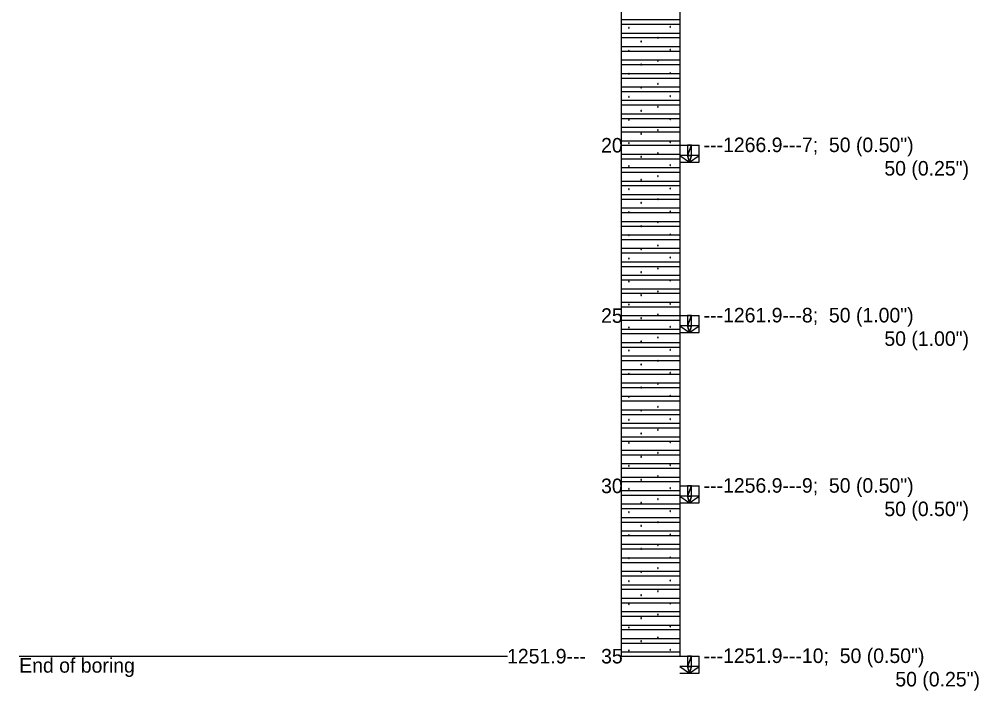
# Model space of a CAD drawing. Extents: x -6 to 173, y 24 to 64.
# Drawn here: x 138.22 to 146.4, y 39.13 to 44.86 of the extents above; entities that cross this region are included whole.
import ezdxf

# ---------------------------------------------------------------- set-up
doc = ezdxf.new("R2010")
doc.units = 0

msp = doc.modelspace()

# ---------------------------------------------------------------- linework, layer by layer
for points in [[(143.3519, 49.5977), (143.3519, 39.4233)], [(143.8519, 49.5977), (143.8519, 39.4233)], [(143.3519, 44.8563), (143.8519, 44.8563)], [(143.3519, 44.817), (143.8519, 44.817)], [(143.4223, 44.7872), (143.4206, 44.79), (143.4174, 44.79), (143.4157, 44.7872), (143.4174, 44.7843), (143.4206, 44.7843), (143.4223, 44.7872)], [(143.775, 44.7937), (143.7734, 44.7966), (143.7701, 44.7966), (143.7685, 44.7937), (143.7701, 44.7908), (143.7734, 44.7908), (143.775, 44.7937)], [(143.3519, 44.7415), (143.8519, 44.7415)], [(143.3519, 44.7021), (143.8519, 44.7021)], [(143.6695, 44.7012), (143.6679, 44.704), (143.6646, 44.704), (143.663, 44.7012), (143.6646, 44.6983), (143.6679, 44.6983), (143.6695, 44.7012)], [(143.3519, 44.6267), (143.8519, 44.6267)], [(143.5269, 44.6693), (143.5253, 44.6721), (143.522, 44.6721), (143.5204, 44.6693), (143.522, 44.6664), (143.5253, 44.6664), (143.5269, 44.6693)], [(143.3519, 44.5873), (143.8519, 44.5873)], [(143.4223, 44.5903), (143.4206, 44.5931), (143.4174, 44.5931), (143.4157, 44.5903), (143.4174, 44.5874), (143.4206, 44.5874), (143.4223, 44.5903)], [(143.775, 44.5968), (143.7734, 44.5997), (143.7701, 44.5997), (143.7685, 44.5968), (143.7701, 44.594), (143.7734, 44.594), (143.775, 44.5968)], [(143.3519, 44.5118), (143.8519, 44.5118)], [(143.3519, 44.4725), (143.8519, 44.4725)], [(143.5269, 44.4724), (143.5253, 44.4753), (143.522, 44.4753), (143.5204, 44.4725), (143.522, 44.4696), (143.5253, 44.4696), (143.5269, 44.4724)], [(143.6695, 44.5043), (143.6679, 44.5071), (143.6646, 44.5071), (143.663, 44.5043), (143.6646, 44.5015), (143.6679, 44.5015), (143.6695, 44.5043)], [(143.3519, 44.397), (143.8519, 44.397)], [(143.4223, 44.3935), (143.4206, 44.3963), (143.4174, 44.3963), (143.4157, 44.3935), (143.4174, 44.3906), (143.4206, 44.3906), (143.4223, 44.3935)], [(143.775, 44.4), (143.7734, 44.4029), (143.7701, 44.4029), (143.7685, 44.4), (143.7701, 44.3971), (143.7734, 44.3971), (143.775, 44.4)], [(143.3519, 44.3576), (143.8519, 44.3576)], [(143.6695, 44.3075), (143.6679, 44.3103), (143.6646, 44.3103), (143.663, 44.3075), (143.6646, 44.3046), (143.6679, 44.3046), (143.6695, 44.3075)], [(143.3519, 44.2822), (143.8519, 44.2822)], [(143.3519, 44.2428), (143.8519, 44.2428)], [(143.5269, 44.2756), (143.5253, 44.2784), (143.522, 44.2784), (143.5204, 44.2756), (143.522, 44.2727), (143.5253, 44.2727), (143.5269, 44.2756)], [(143.775, 44.2031), (143.7734, 44.206), (143.7701, 44.206), (143.7685, 44.2031), (143.7701, 44.2003), (143.7734, 44.2003), (143.775, 44.2031)], [(143.3519, 44.1674), (143.8519, 44.1674)], [(143.3519, 44.128), (143.8519, 44.128)], [(143.4223, 44.1966), (143.4206, 44.1994), (143.4174, 44.1994), (143.4157, 44.1966), (143.4174, 44.1937), (143.4206, 44.1937), (143.4223, 44.1966)], [(143.3519, 44.0525), (143.8519, 44.0525)], [(143.5269, 44.0787), (143.5253, 44.0816), (143.522, 44.0816), (143.5204, 44.0788), (143.522, 44.0759), (143.5253, 44.0759), (143.5269, 44.0787)], [(143.6695, 44.1106), (143.6679, 44.1134), (143.6646, 44.1134), (143.663, 44.1106), (143.6646, 44.1078), (143.6679, 44.1078), (143.6695, 44.1106)], [(143.3519, 44.0132), (143.8519, 44.0132)], [(143.4223, 43.9998), (143.4206, 44.0026), (143.4174, 44.0026), (143.4157, 43.9998), (143.4174, 43.9969), (143.4206, 43.9969), (143.4223, 43.9998)], [(143.775, 44.0063), (143.7734, 44.0092), (143.7701, 44.0092), (143.7685, 44.0063), (143.7701, 44.0034), (143.7734, 44.0034), (143.775, 44.0063)], [(143.3519, 43.9377), (143.8519, 43.9377)], [(143.3519, 43.8983), (143.8519, 43.8983)], [(143.5269, 43.8819), (143.5253, 43.8847), (143.522, 43.8847), (143.5204, 43.8819), (143.522, 43.879), (143.5253, 43.879), (143.5269, 43.8819)], [(143.6695, 43.9137), (143.6679, 43.9166), (143.6646, 43.9166), (143.663, 43.9137), (143.6646, 43.9109), (143.6679, 43.9109), (143.6695, 43.9137)], [(143.3519, 43.8229), (143.8519, 43.8229)], [(143.4223, 43.8029), (143.4206, 43.8057), (143.4174, 43.8057), (143.4157, 43.8029), (143.4174, 43.8), (143.4206, 43.8), (143.4223, 43.8029)], [(143.775, 43.8094), (143.7734, 43.8123), (143.7701, 43.8123), (143.7685, 43.8094), (143.7701, 43.8066), (143.7734, 43.8066), (143.775, 43.8094)], [(143.3519, 43.7835), (143.8519, 43.7835)], [(143.6695, 43.7169), (143.6679, 43.7197), (143.6646, 43.7197), (143.663, 43.7169), (143.6646, 43.7141), (143.6679, 43.7141), (143.6695, 43.7169)], [(143.8519, 43.7838), (144.0185, 43.7838)], [(144.0185, 43.6384), (144.0185, 43.7838)], [(143.3519, 43.708), (143.8519, 43.708)], [(143.3519, 43.6687), (143.8519, 43.6687)], [(143.5269, 43.685), (143.5253, 43.6879), (143.522, 43.6879), (143.5204, 43.6851), (143.522, 43.6822), (143.5253, 43.6822), (143.5269, 43.685)], [(143.8519, 43.6384), (144.0185, 43.6384)], [(143.3519, 43.5932), (143.8519, 43.5932)], [(143.3519, 43.5538), (143.8519, 43.5538)], [(143.4223, 43.6061), (143.4206, 43.6089), (143.4174, 43.6089), (143.4157, 43.6061), (143.4174, 43.6032), (143.4206, 43.6032), (143.4223, 43.6061)], [(143.775, 43.6126), (143.7734, 43.6155), (143.7701, 43.6155), (143.7685, 43.6126), (143.7701, 43.6097), (143.7734, 43.6097), (143.775, 43.6126)], [(143.3519, 43.4784), (143.8519, 43.4784)], [(143.5269, 43.4882), (143.5253, 43.491), (143.522, 43.491), (143.5204, 43.4882), (143.522, 43.4853), (143.5253, 43.4853), (143.5269, 43.4882)], [(143.6695, 43.52), (143.6679, 43.5229), (143.6646, 43.5229), (143.663, 43.52), (143.6646, 43.5172), (143.6679, 43.5172), (143.6695, 43.52)], [(143.3519, 43.439), (143.8519, 43.439)], [(143.4223, 43.4092), (143.4206, 43.412), (143.4174, 43.412), (143.4157, 43.4092), (143.4174, 43.4063), (143.4206, 43.4063), (143.4223, 43.4092)], [(143.775, 43.4157), (143.7734, 43.4186), (143.7701, 43.4186), (143.7685, 43.4157), (143.7701, 43.4129), (143.7734, 43.4129), (143.775, 43.4157)], [(143.3519, 43.3636), (143.8519, 43.3636)], [(143.3519, 43.3242), (143.8519, 43.3242)], [(143.6695, 43.3232), (143.6679, 43.326), (143.6646, 43.326), (143.663, 43.3232), (143.6646, 43.3204), (143.6679, 43.3204), (143.6695, 43.3232)], [(143.3519, 43.2487), (143.8519, 43.2487)], [(143.5269, 43.2913), (143.5253, 43.2942), (143.522, 43.2942), (143.5204, 43.2914), (143.522, 43.2885), (143.5253, 43.2885), (143.5269, 43.2913)], [(143.3519, 43.2094), (143.8519, 43.2094)], [(143.4223, 43.2124), (143.4206, 43.2152), (143.4174, 43.2152), (143.4157, 43.2124), (143.4174, 43.2095), (143.4206, 43.2095), (143.4223, 43.2124)], [(143.775, 43.2189), (143.7734, 43.2218), (143.7701, 43.2218), (143.7685, 43.2189), (143.7701, 43.216), (143.7734, 43.216), (143.775, 43.2189)], [(143.3519, 43.1339), (143.8519, 43.1339)], [(143.3519, 43.0945), (143.8519, 43.0945)], [(143.5269, 43.0945), (143.5253, 43.0973), (143.522, 43.0973), (143.5204, 43.0945), (143.522, 43.0916), (143.5253, 43.0916), (143.5269, 43.0945)], [(143.6695, 43.1263), (143.6679, 43.1292), (143.6646, 43.1292), (143.663, 43.1263), (143.6646, 43.1235), (143.6679, 43.1235), (143.6695, 43.1263)], [(143.3519, 43.0191), (143.8519, 43.0191)], [(143.3519, 42.9797), (143.8519, 42.9797)], [(143.4223, 43.0155), (143.4206, 43.0183), (143.4174, 43.0183), (143.4157, 43.0155), (143.4174, 43.0126), (143.4206, 43.0126), (143.4223, 43.0155)], [(143.775, 43.022), (143.7734, 43.0249), (143.7701, 43.0249), (143.7685, 43.022), (143.7701, 43.0192), (143.7734, 43.0192), (143.775, 43.022)], [(143.3519, 42.9042), (143.8519, 42.9042)], [(143.5269, 42.8976), (143.5253, 42.9005), (143.522, 42.9005), (143.5204, 42.8977), (143.522, 42.8948), (143.5253, 42.8948), (143.5269, 42.8976)], [(143.6695, 42.9295), (143.6679, 42.9323), (143.6646, 42.9323), (143.663, 42.9295), (143.6646, 42.9267), (143.6679, 42.9267), (143.6695, 42.9295)], [(143.3519, 42.8649), (143.8519, 42.8649)], [(143.4223, 42.8187), (143.4206, 42.8215), (143.4174, 42.8215), (143.4157, 42.8187), (143.4174, 42.8158), (143.4206, 42.8158), (143.4223, 42.8187)], [(143.775, 42.8252), (143.7734, 42.8281), (143.7701, 42.8281), (143.7685, 42.8252), (143.7701, 42.8223), (143.7734, 42.8223), (143.775, 42.8252)], [(143.3519, 42.7894), (143.8519, 42.7894)], [(143.3519, 42.75), (143.8519, 42.75)], [(143.6695, 42.7326), (143.6679, 42.7355), (143.6646, 42.7355), (143.663, 42.7326), (143.6646, 42.7298), (143.6679, 42.7298), (143.6695, 42.7326)], [(143.3519, 42.6746), (143.8519, 42.6746)], [(143.5269, 42.7008), (143.5253, 42.7036), (143.522, 42.7036), (143.5204, 42.7008), (143.522, 42.6979), (143.5253, 42.6979), (143.5269, 42.7008)], [(143.3519, 42.6352), (143.8519, 42.6352)], [(143.4223, 42.6218), (143.4206, 42.6246), (143.4174, 42.6246), (143.4157, 42.6218), (143.4174, 42.6189), (143.4206, 42.6189), (143.4223, 42.6218)], [(143.775, 42.6283), (143.7734, 42.6312), (143.7701, 42.6312), (143.7685, 42.6283), (143.7701, 42.6255), (143.7734, 42.6255), (143.775, 42.6283)], [(143.3519, 42.5597), (143.8519, 42.5597)], [(143.3519, 42.5204), (143.8519, 42.5204)], [(143.5269, 42.5039), (143.5253, 42.5068), (143.522, 42.5068), (143.5204, 42.504), (143.522, 42.5011), (143.5253, 42.5011), (143.5269, 42.5039)], [(143.6695, 42.5358), (143.6679, 42.5386), (143.6646, 42.5386), (143.663, 42.5358), (143.6646, 42.533), (143.6679, 42.533), (143.6695, 42.5358)], [(143.3519, 42.4449), (143.8519, 42.4449)], [(143.3519, 42.4055), (143.8519, 42.4055)], [(143.4223, 42.425), (143.4206, 42.4278), (143.4174, 42.4278), (143.4157, 42.425), (143.4174, 42.4221), (143.4206, 42.4221), (143.4223, 42.425)], [(143.775, 42.4315), (143.7734, 42.4344), (143.7701, 42.4344), (143.7685, 42.4315), (143.7701, 42.4286), (143.7734, 42.4286), (143.775, 42.4315)], [(143.3519, 42.3301), (143.8519, 42.3301)], [(143.6695, 42.3389), (143.6679, 42.3418), (143.6646, 42.3418), (143.663, 42.3389), (143.6646, 42.3361), (143.6679, 42.3361), (143.6695, 42.3389)], [(143.8519, 42.3303), (144.0185, 42.3303)], [(144.0185, 42.1849), (144.0185, 42.3303)], [(143.3519, 42.2907), (143.8519, 42.2907)], [(143.5269, 42.3071), (143.5253, 42.3099), (143.522, 42.3099), (143.5204, 42.3071), (143.522, 42.3042), (143.5253, 42.3042), (143.5269, 42.3071)], [(143.3519, 42.2153), (143.8519, 42.2153)], [(143.3519, 42.1759), (143.8519, 42.1759)], [(143.4223, 42.2281), (143.4206, 42.2309), (143.4174, 42.2309), (143.4157, 42.2281), (143.4174, 42.2252), (143.4206, 42.2252), (143.4223, 42.2281)], [(143.775, 42.2346), (143.7734, 42.2375), (143.7701, 42.2375), (143.7685, 42.2346), (143.7701, 42.2318), (143.7734, 42.2318), (143.775, 42.2346)], [(143.8519, 42.1849), (144.0185, 42.1849)], [(143.3519, 42.1004), (143.8519, 42.1004)], [(143.5269, 42.1102), (143.5253, 42.1131), (143.522, 42.1131), (143.5204, 42.1103), (143.522, 42.1074), (143.5253, 42.1074), (143.5269, 42.1102)], [(143.6695, 42.1421), (143.6679, 42.1449), (143.6646, 42.1449), (143.663, 42.1421), (143.6646, 42.1393), (143.6679, 42.1393), (143.6695, 42.1421)], [(143.3519, 42.0611), (143.8519, 42.0611)], [(143.4223, 42.0313), (143.4206, 42.0341), (143.4174, 42.0341), (143.4157, 42.0313), (143.4174, 42.0284), (143.4206, 42.0284), (143.4223, 42.0313)], [(143.775, 42.0378), (143.7734, 42.0407), (143.7701, 42.0407), (143.7685, 42.0378), (143.7701, 42.0349), (143.7734, 42.0349), (143.775, 42.0378)], [(143.3519, 41.9856), (143.8519, 41.9856)], [(143.3519, 41.9462), (143.8519, 41.9462)], [(143.5269, 41.9134), (143.5253, 41.9162), (143.522, 41.9162), (143.5204, 41.9134), (143.522, 41.9105), (143.5253, 41.9105), (143.5269, 41.9134)], [(143.6695, 41.9452), (143.6679, 41.9481), (143.6646, 41.9481), (143.663, 41.9452), (143.6646, 41.9424), (143.6679, 41.9424), (143.6695, 41.9452)], [(143.3519, 41.8708), (143.8519, 41.8708)], [(143.3519, 41.8314), (143.8519, 41.8314)], [(143.4223, 41.8344), (143.4206, 41.8372), (143.4174, 41.8372), (143.4157, 41.8344), (143.4174, 41.8315), (143.4206, 41.8315), (143.4223, 41.8344)], [(143.775, 41.8409), (143.7734, 41.8438), (143.7701, 41.8438), (143.7685, 41.8409), (143.7701, 41.8381), (143.7734, 41.8381), (143.775, 41.8409)], [(143.3519, 41.7559), (143.8519, 41.7559)], [(143.6695, 41.7484), (143.6679, 41.7512), (143.6646, 41.7512), (143.663, 41.7484), (143.6646, 41.7456), (143.6679, 41.7456), (143.6695, 41.7484)], [(143.3519, 41.7166), (143.8519, 41.7166)], [(143.5269, 41.7165), (143.5253, 41.7194), (143.522, 41.7194), (143.5204, 41.7166), (143.522, 41.7137), (143.5253, 41.7137), (143.5269, 41.7165)], [(143.3519, 41.6411), (143.8519, 41.6411)], [(143.3519, 41.6017), (143.8519, 41.6017)], [(143.4223, 41.6376), (143.4206, 41.6404), (143.4174, 41.6404), (143.4157, 41.6376), (143.4174, 41.6347), (143.4206, 41.6347), (143.4223, 41.6376)], [(143.775, 41.6441), (143.7734, 41.647), (143.7701, 41.647), (143.7685, 41.6441), (143.7701, 41.6412), (143.7734, 41.6412), (143.775, 41.6441)], [(143.3519, 41.5263), (143.8519, 41.5263)], [(143.5269, 41.5197), (143.5253, 41.5225), (143.522, 41.5225), (143.5204, 41.5197), (143.522, 41.5168), (143.5253, 41.5168), (143.5269, 41.5197)], [(143.6695, 41.5515), (143.6679, 41.5544), (143.6646, 41.5544), (143.663, 41.5515), (143.6646, 41.5487), (143.6679, 41.5487), (143.6695, 41.5515)], [(143.3519, 41.4869), (143.8519, 41.4869)], [(143.4223, 41.4407), (143.4206, 41.4435), (143.4174, 41.4435), (143.4157, 41.4407), (143.4174, 41.4378), (143.4206, 41.4378), (143.4223, 41.4407)], [(143.775, 41.4472), (143.7734, 41.4501), (143.7701, 41.4501), (143.7685, 41.4472), (143.7701, 41.4444), (143.7734, 41.4444), (143.775, 41.4472)], [(143.3519, 41.4115), (143.8519, 41.4115)], [(143.3519, 41.3721), (143.8519, 41.3721)], [(143.6695, 41.3547), (143.6679, 41.3575), (143.6646, 41.3575), (143.663, 41.3547), (143.6646, 41.3519), (143.6679, 41.3519), (143.6695, 41.3547)], [(143.3519, 41.2966), (143.8519, 41.2966)], [(143.5269, 41.3228), (143.5253, 41.3257), (143.522, 41.3257), (143.5204, 41.3229), (143.522, 41.32), (143.5253, 41.32), (143.5269, 41.3228)], [(143.3519, 41.2573), (143.8519, 41.2573)], [(143.3519, 41.1818), (143.8519, 41.1818)], [(143.4223, 41.2439), (143.4206, 41.2467), (143.4174, 41.2467), (143.4157, 41.2439), (143.4174, 41.241), (143.4206, 41.241), (143.4223, 41.2439)], [(143.775, 41.2504), (143.7734, 41.2533), (143.7701, 41.2533), (143.7685, 41.2504), (143.7701, 41.2475), (143.7734, 41.2475), (143.775, 41.2504)], [(143.3519, 41.1424), (143.8519, 41.1424)], [(143.5269, 41.126), (143.5253, 41.1288), (143.522, 41.1288), (143.5204, 41.126), (143.522, 41.1231), (143.5253, 41.1231), (143.5269, 41.126)], [(143.6695, 41.1578), (143.6679, 41.1607), (143.6646, 41.1607), (143.663, 41.1578), (143.6646, 41.155), (143.6679, 41.155), (143.6695, 41.1578)], [(143.3519, 41.067), (143.8519, 41.067)], [(143.3519, 41.0276), (143.8519, 41.0276)], [(143.4223, 41.047), (143.4206, 41.0498), (143.4174, 41.0498), (143.4157, 41.047), (143.4174, 41.0441), (143.4206, 41.0441), (143.4223, 41.047)], [(143.775, 41.0535), (143.7734, 41.0564), (143.7701, 41.0564), (143.7685, 41.0535), (143.7701, 41.0507), (143.7734, 41.0507), (143.775, 41.0535)], [(143.3519, 40.9521), (143.8519, 40.9521)], [(143.5269, 40.9291), (143.5253, 40.932), (143.522, 40.932), (143.5204, 40.9292), (143.522, 40.9263), (143.5253, 40.9263), (143.5269, 40.9291)], [(143.6695, 40.961), (143.6679, 40.9638), (143.6646, 40.9638), (143.663, 40.961), (143.6646, 40.9582), (143.6679, 40.9582), (143.6695, 40.961)], [(143.3519, 40.9128), (143.8519, 40.9128)], [(143.4223, 40.8502), (143.4206, 40.853), (143.4174, 40.853), (143.4157, 40.8502), (143.4174, 40.8473), (143.4206, 40.8473), (143.4223, 40.8502)], [(143.775, 40.8567), (143.7734, 40.8596), (143.7701, 40.8596), (143.7685, 40.8567), (143.7701, 40.8538), (143.7734, 40.8538), (143.775, 40.8567)], [(143.8519, 40.8768), (144.0185, 40.8768)], [(144.0185, 40.7314), (144.0185, 40.8768)], [(143.3519, 40.8373), (143.8519, 40.8373)], [(143.3519, 40.7979), (143.8519, 40.7979)], [(143.6695, 40.7641), (143.6679, 40.767), (143.6646, 40.767), (143.663, 40.7641), (143.6646, 40.7613), (143.6679, 40.7613), (143.6695, 40.7641)], [(143.3519, 40.7225), (143.8519, 40.7225)], [(143.5269, 40.7323), (143.5253, 40.7351), (143.522, 40.7351), (143.5204, 40.7323), (143.522, 40.7294), (143.5253, 40.7294), (143.5269, 40.7323)], [(143.8519, 40.7314), (144.0185, 40.7314)], [(143.3519, 40.6831), (143.8519, 40.6831)], [(143.3519, 40.6076), (143.8519, 40.6076)], [(143.4223, 40.6533), (143.4206, 40.6561), (143.4174, 40.6561), (143.4157, 40.6533), (143.4174, 40.6504), (143.4206, 40.6504), (143.4223, 40.6533)], [(143.775, 40.6598), (143.7734, 40.6627), (143.7701, 40.6627), (143.7685, 40.6598), (143.7701, 40.657), (143.7734, 40.657), (143.775, 40.6598)], [(143.3519, 40.5683), (143.8519, 40.5683)], [(143.5269, 40.5354), (143.5253, 40.5383), (143.522, 40.5383), (143.5204, 40.5355), (143.522, 40.5326), (143.5253, 40.5326), (143.5269, 40.5354)], [(143.6695, 40.5673), (143.6679, 40.5701), (143.6646, 40.5701), (143.663, 40.5673), (143.6646, 40.5645), (143.6679, 40.5645), (143.6695, 40.5673)], [(143.3519, 40.4928), (143.8519, 40.4928)], [(143.3519, 40.4534), (143.8519, 40.4534)], [(143.4223, 40.4565), (143.4206, 40.4593), (143.4174, 40.4593), (143.4157, 40.4565), (143.4174, 40.4536), (143.4206, 40.4536), (143.4223, 40.4565)], [(143.775, 40.463), (143.7734, 40.4658), (143.7701, 40.4658), (143.7685, 40.463), (143.7701, 40.4601), (143.7734, 40.4601), (143.775, 40.463)], [(143.3519, 40.378), (143.8519, 40.378)], [(143.6695, 40.3704), (143.6679, 40.3733), (143.6646, 40.3733), (143.663, 40.3704), (143.6646, 40.3676), (143.6679, 40.3676), (143.6695, 40.3704)], [(143.3519, 40.3386), (143.8519, 40.3386)], [(143.5269, 40.3386), (143.5253, 40.3414), (143.522, 40.3414), (143.5204, 40.3386), (143.522, 40.3357), (143.5253, 40.3357), (143.5269, 40.3386)], [(143.3519, 40.2632), (143.8519, 40.2632)], [(143.3519, 40.2238), (143.8519, 40.2238)], [(143.4223, 40.2596), (143.4206, 40.2624), (143.4174, 40.2624), (143.4157, 40.2596), (143.4174, 40.2567), (143.4206, 40.2567), (143.4223, 40.2596)], [(143.775, 40.2661), (143.7734, 40.269), (143.7701, 40.269), (143.7685, 40.2661), (143.7701, 40.2633), (143.7734, 40.2633), (143.775, 40.2661)], [(143.3519, 40.1483), (143.8519, 40.1483)], [(143.5269, 40.1417), (143.5253, 40.1446), (143.522, 40.1446), (143.5204, 40.1418), (143.522, 40.1389), (143.5253, 40.1389), (143.5269, 40.1417)], [(143.6695, 40.1736), (143.6679, 40.1764), (143.6646, 40.1764), (143.663, 40.1736), (143.6646, 40.1708), (143.6679, 40.1708), (143.6695, 40.1736)], [(143.3519, 40.109), (143.8519, 40.109)], [(143.3519, 40.0335), (143.8519, 40.0335)], [(143.4223, 40.0628), (143.4206, 40.0656), (143.4174, 40.0656), (143.4157, 40.0628), (143.4174, 40.0599), (143.4206, 40.0599), (143.4223, 40.0628)], [(143.775, 40.0693), (143.7734, 40.0721), (143.7701, 40.0721), (143.7685, 40.0693), (143.7701, 40.0664), (143.7734, 40.0664), (143.775, 40.0693)], [(143.3519, 39.9941), (143.8519, 39.9941)], [(143.6695, 39.9767), (143.6679, 39.9796), (143.6646, 39.9796), (143.663, 39.9767), (143.6646, 39.9739), (143.6679, 39.9739), (143.6695, 39.9767)], [(143.3519, 39.9187), (143.8519, 39.9187)], [(143.3519, 39.8793), (143.8519, 39.8793)], [(143.4223, 39.8659), (143.4206, 39.8687), (143.4174, 39.8687), (143.4157, 39.8659), (143.4174, 39.863), (143.4206, 39.863), (143.4223, 39.8659)], [(143.5269, 39.9449), (143.5253, 39.9477), (143.522, 39.9477), (143.5204, 39.9449), (143.522, 39.942), (143.5253, 39.942), (143.5269, 39.9449)], [(143.775, 39.8724), (143.7734, 39.8753), (143.7701, 39.8753), (143.7685, 39.8724), (143.7701, 39.8696), (143.7734, 39.8696), (143.775, 39.8724)], [(143.3519, 39.8038), (143.8519, 39.8038)], [(143.3519, 39.7645), (143.8519, 39.7645)], [(143.5269, 39.748), (143.5253, 39.7509), (143.522, 39.7509), (143.5204, 39.7481), (143.522, 39.7452), (143.5253, 39.7452), (143.5269, 39.748)], [(143.6695, 39.7799), (143.6679, 39.7827), (143.6646, 39.7827), (143.663, 39.7799), (143.6646, 39.7771), (143.6679, 39.7771), (143.6695, 39.7799)], [(143.3519, 39.689), (143.8519, 39.689)], [(143.3519, 39.6496), (143.8519, 39.6496)], [(143.4223, 39.6691), (143.4206, 39.6719), (143.4174, 39.6719), (143.4157, 39.6691), (143.4174, 39.6662), (143.4206, 39.6662), (143.4223, 39.6691)], [(143.775, 39.6756), (143.7734, 39.6784), (143.7701, 39.6784), (143.7685, 39.6756), (143.7701, 39.6727), (143.7734, 39.6727), (143.775, 39.6756)], [(143.3519, 39.5742), (143.8519, 39.5742)], [(143.5269, 39.5512), (143.5253, 39.554), (143.522, 39.554), (143.5204, 39.5512), (143.522, 39.5483), (143.5253, 39.5483), (143.5269, 39.5512)], [(143.6695, 39.583), (143.6679, 39.5859), (143.6646, 39.5859), (143.663, 39.583), (143.6646, 39.5802), (143.6679, 39.5802), (143.6695, 39.583)], [(143.3519, 39.5348), (143.8519, 39.5348)], [(143.3519, 39.4594), (143.8519, 39.4594)], [(143.4223, 39.4722), (143.4206, 39.475), (143.4174, 39.475), (143.4157, 39.4722), (143.4174, 39.4693), (143.4206, 39.4693), (143.4223, 39.4722)], [(143.775, 39.4787), (143.7734, 39.4816), (143.7701, 39.4816), (143.7685, 39.4787), (143.7701, 39.4759), (143.7734, 39.4759), (143.775, 39.4787)], [(138.2177, 39.4233), (142.3844, 39.4233)], [(143.3519, 39.4233), (143.8519, 39.4233)], [(143.8519, 39.4233), (144.0185, 39.4233)], [(144.0185, 39.278), (144.0185, 39.4233)], [(143.8519, 39.278), (144.0185, 39.278)]]:
    msp.add_lwpolyline(points)
for points in [[(143.9185, 43.6966), (143.9519, 43.6966), (143.9519, 43.7838), (143.9185, 43.6966)], [(143.9185, 43.6966), (143.9519, 43.7838), (143.9185, 43.7838), (143.9185, 43.6966)], [(143.9185, 43.6966), (143.8519, 43.6966), (143.9352, 43.6384), (143.9185, 43.6966)], [(143.9185, 43.6966), (143.9352, 43.6384), (143.9519, 43.6966), (143.9185, 43.6966)], [(143.9352, 43.6384), (144.0185, 43.6966), (143.9519, 43.6966), (143.9352, 43.6384)], [(143.9185, 42.2431), (143.9519, 42.2431), (143.9519, 42.3303), (143.9185, 42.2431)], [(143.9185, 42.2431), (143.9519, 42.3303), (143.9185, 42.3303), (143.9185, 42.2431)], [(143.9185, 42.2431), (143.8519, 42.2431), (143.9352, 42.1849), (143.9185, 42.2431)], [(143.9185, 42.2431), (143.9352, 42.1849), (143.9519, 42.2431), (143.9185, 42.2431)], [(143.9352, 42.1849), (144.0185, 42.2431), (143.9519, 42.2431), (143.9352, 42.1849)], [(143.9185, 40.7896), (143.9519, 40.7896), (143.9519, 40.8768), (143.9185, 40.7896)], [(143.9185, 40.7896), (143.9519, 40.8768), (143.9185, 40.8768), (143.9185, 40.7896)], [(143.9185, 40.7896), (143.8519, 40.7896), (143.9352, 40.7314), (143.9185, 40.7896)], [(143.9185, 40.7896), (143.9352, 40.7314), (143.9519, 40.7896), (143.9185, 40.7896)], [(143.9352, 40.7314), (144.0185, 40.7896), (143.9519, 40.7896), (143.9352, 40.7314)], [(143.9185, 39.3361), (143.9519, 39.3361), (143.9519, 39.4233), (143.9185, 39.3361)], [(143.9185, 39.3361), (143.9519, 39.4233), (143.9185, 39.4233), (143.9185, 39.3361)], [(143.9185, 39.3361), (143.8519, 39.3361), (143.9352, 39.278), (143.9185, 39.3361)], [(143.9185, 39.3361), (143.9352, 39.278), (143.9519, 39.3361), (143.9185, 39.3361)], [(143.9352, 39.278), (144.0185, 39.3361), (143.9519, 39.3361), (143.9352, 39.278)]]:
    msp.add_lwpolyline(points, close=True)

# ---------------------------------------------------------------- texts
for s, p in [('20', (143.1815, 43.7218)), ('---1266.9---7;  50 (0.50")', (144.0562, 43.7254)), ('50 (0.25")', (145.5979, 43.5254)), ('25', (143.1815, 42.2683)), ('---1261.9---8;  50 (1.00")', (144.0562, 42.2719)), ('50 (1.00")', (145.5979, 42.0719)), ('30', (143.1815, 40.8148)), ('---1256.9---9;  50 (0.50")', (144.0562, 40.8185)), ('50 (0.50")', (145.5979, 40.6185)), ('1251.9---', (142.3795, 39.3613)), ('35', (143.1815, 39.3613)), ('---1251.9---10;  50 (0.50")', (144.0562, 39.365)), ('End of boring', (138.2177, 39.2826)), ('50 (0.25")', (145.6915, 39.165))]:
    msp.add_text(s, height=0.124).set_placement(p)

doc.saveas('drawing.dxf')
